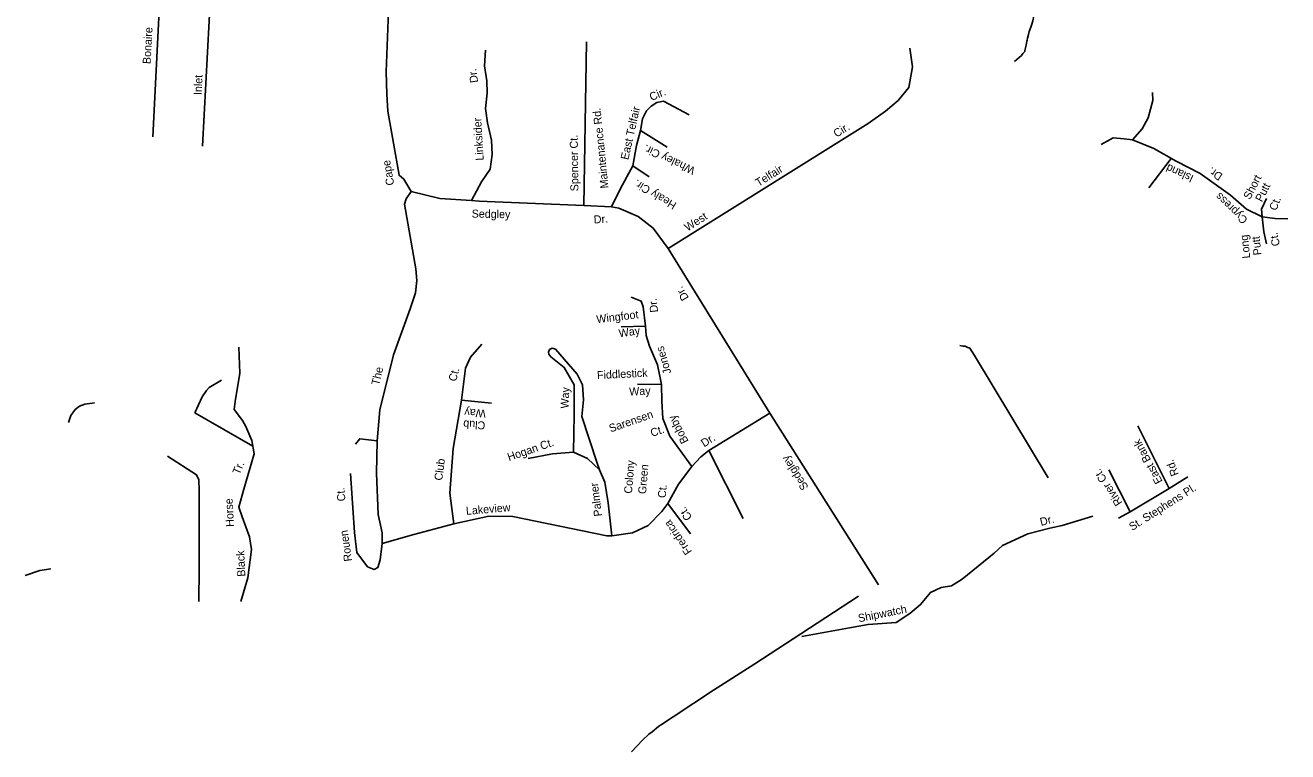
# Model space of a CAD drawing. Extents: x 2308163 to 2335412, y -96774 to 127732.
# Drawn here: x 2322672.99 to 2322693.21, y 104406.26 to 104417.9 of the extents above; entities that cross this region are included whole.
import ezdxf

# ---------------------------------------------------------------- set-up
doc = ezdxf.new("R2010")
doc.units = 0
doc.layers.add('Old_Level_10', color=7, linetype='Continuous')
doc.layers.add('Old_Level_35', color=7, linetype='Continuous')

msp = doc.modelspace()

# ---------------------------------------------------------------- linework, layer by layer
at = {"layer": 'Old_Level_35'}
for points in [[(2322675.83, 104415.962), (2322675.96, 104418.478), (2322676.033, 104419.348), (2322676.035, 104420.25), (2322676.11, 104421.179), (2322676.041, 104422.069), (2322676.047, 104422.656), (2322676.193, 104423.152), (2322676.251, 104423.594), (2322676.259, 104424.238)], [(2322675.033, 104416.113), (2322675.401, 104423.451), (2322675.323, 104424.098)], [(2322679.171, 104415.235), (2322679.055, 104415.435), (2322678.976, 104415.495), (2322678.798, 104416.524), (2322678.783, 104416.794), (2322678.771, 104417.155), (2322678.8, 104417.988), (2322678.79, 104418.201), (2322678.759, 104418.726), (2322678.726, 104419.169), (2322678.742, 104419.406), (2322678.832, 104419.64), (2322679.021, 104419.887), (2322679.16, 104420.128), (2322679.286, 104420.459), (2322679.438, 104421.059), (2322679.59, 104421.675), (2322679.797, 104422.47), (2322679.971, 104423.233), (2322680.03, 104423.664)], [(2322689.036, 104417.658), (2322689.046, 104417.691), (2322689.059, 104417.749), (2322689.072, 104417.8), (2322689.097, 104417.869), (2322689.118, 104417.935), (2322689.131, 104417.97), (2322689.135, 104417.997), (2322689.14, 104418.02), (2322689.136, 104418.056), (2322689.141, 104418.095), (2322689.126, 104418.248), (2322689.101, 104418.506), (2322689.068, 104418.796), (2322689.055, 104418.894), (2322689.055, 104419.023), (2322689.051, 104419.176), (2322689.06, 104419.429), (2322689.074, 104419.828), (2322689.099, 104420.394), (2322689.114, 104420.792)], [(2322681.936, 104415.013), (2322681.979, 104417.635)], [(2322683.287, 104414.32), (2322686.492, 104416.326), (2322686.769, 104416.521), (2322686.972, 104416.694), (2322687.142, 104416.9), (2322687.203, 104417.234), (2322687.156, 104417.53)], [(2322688.834, 104417.321), (2322688.945, 104417.415), (2322688.969, 104417.446), (2322688.989, 104417.47), (2322689.001, 104417.48), (2322689.002, 104417.496), (2322689.02, 104417.582), (2322689.033, 104417.644), (2322689.036, 104417.658)], [(2322680.361, 104417.501), (2322680.344, 104417.248), (2322680.385, 104417.009), (2322680.387, 104416.813), (2322680.362, 104416.568), (2322680.395, 104416.338), (2322680.459, 104416.058), (2322680.467, 104415.828), (2322680.435, 104415.592), (2322680.297, 104415.392), (2322680.139, 104415.092)], [(2322690.724, 104416.061), (2322690.879, 104416.238), (2322690.976, 104416.417), (2322691.052, 104416.696), (2322691.048, 104416.82)], [(2322682.377, 104414.99), (2322682.526, 104415.284), (2322682.719, 104415.646), (2322682.779, 104415.971), (2322682.845, 104416.214), (2322682.876, 104416.401), (2322682.938, 104416.53), (2322683.014, 104416.601), (2322683.106, 104416.663), (2322683.213, 104416.684), (2322683.623, 104416.466)], [(2322682.845, 104416.214), (2322683.27, 104415.946)], [(2322690.223, 104415.987), (2322690.418, 104416.096), (2322690.592, 104416.082), (2322690.724, 104416.061), (2322691.067, 104415.924), (2322691.425, 104415.722), (2322691.808, 104415.526), (2322692.294, 104415.178), (2322692.552, 104414.953), (2322692.804, 104414.829), (2322692.792, 104414.953), (2322692.873, 104415.125)], [(2322690.988, 104415.297), (2322691.347, 104415.766)], [(2322682.719, 104415.646), (2322682.983, 104415.473)], [(2322679.171, 104415.235), (2322679.093, 104415.116), (2322679.066, 104415.035), (2322679.243, 104413.999), (2322679.261, 104413.81), (2322679.238, 104413.614), (2322679.156, 104413.355), (2322678.885, 104412.62), (2322678.666, 104411.737), (2322678.624, 104411.24), (2322678.614, 104410.725), (2322678.641, 104410.061), (2322678.704, 104409.764), (2322678.706, 104409.593), (2322678.673, 104409.332), (2322678.636, 104409.21), (2322678.578, 104409.18), (2322678.473, 104409.224), (2322678.3, 104409.451), (2322678.262, 104409.771), (2322678.197, 104410.715)], [(2322683.666, 104410.827), (2322683.811, 104410.986), (2322683.937, 104411.088), (2322684.916, 104411.684), (2322683.287, 104414.32), (2322683.045, 104414.648), (2322682.806, 104414.836), (2322682.499, 104414.969), (2322682.377, 104414.99), (2322681.936, 104415.013), (2322680.261, 104415.079), (2322680.139, 104415.092), (2322679.632, 104415.126), (2322679.171, 104415.235)], [(2322692.804, 104414.829), (2322692.829, 104414.587), (2322692.872, 104414.395)], [(2322692.804, 104414.829), (2322693.011, 104414.805), (2322693.212, 104414.796)], [(2322678.706, 104409.593), (2322679.211, 104409.739), (2322679.856, 104409.913), (2322680.416, 104410.033), (2322680.801, 104410.028), (2322681.915, 104409.799), (2322682.305, 104409.72), (2322682.387, 104409.718), (2322682.716, 104409.764), (2322682.966, 104409.886), (2322683.186, 104410.107), (2322683.281, 104410.235), (2322683.452, 104410.548), (2322683.666, 104410.827), (2322683.315, 104411.314), (2322683.202, 104411.596), (2322683.187, 104411.874), (2322683.18, 104412.145), (2322683.117, 104412.458), (2322682.988, 104412.757), (2322682.936, 104412.93), (2322682.925, 104413.078), (2322682.887, 104413.39), (2322682.857, 104413.481), (2322682.696, 104413.544)], [(2322682.925, 104413.078), (2322682.532, 104413.067)], [(2322676.442, 104408.665), (2322676.556, 104409.044), (2322676.615, 104409.5), (2322676.579, 104409.702), (2322676.461, 104410.021), (2322676.409, 104410.18), (2322676.49, 104410.464), (2322676.653, 104411.031), (2322676.618, 104411.247), (2322676.521, 104411.472), (2322676.471, 104411.567), (2322676.334, 104411.743), (2322676.352, 104411.872), (2322676.426, 104412.327), (2322676.411, 104412.743)], [(2322679.856, 104409.913), (2322679.792, 104410.401), (2322679.841, 104411.119), (2322679.975, 104411.892), (2322680.041, 104412.405), (2322680.121, 104412.582), (2322680.3, 104412.789)], [(2322681.772, 104411.061), (2322681.784, 104411.658), (2322681.784, 104412.14), (2322681.622, 104412.416), (2322681.407, 104412.587), (2322681.375, 104412.629), (2322681.368, 104412.662), (2322681.386, 104412.702), (2322681.428, 104412.725), (2322681.485, 104412.707), (2322681.831, 104412.311), (2322681.915, 104412.136), (2322681.931, 104411.898), (2322681.906, 104411.629), (2322682.143, 104410.901), (2322682.188, 104410.777)], [(2322689.372, 104410.648), (2322688.79, 104411.616), (2322688.192, 104412.607), (2322688.121, 104412.723), (2322688.09, 104412.738), (2322688.047, 104412.755), (2322688.008, 104412.76), (2322687.958, 104412.769)], [(2322675.705, 104411.691), (2322675.824, 104411.944), (2322675.893, 104412.046), (2322675.934, 104412.096), (2322676.131, 104412.213)], [(2322683.18, 104412.145), (2322682.795, 104412.15)], [(2322673.683, 104411.533), (2322673.72, 104411.646), (2322673.789, 104411.743), (2322673.86, 104411.794), (2322673.944, 104411.83), (2322674.097, 104411.85)], [(2322679.975, 104411.892), (2322680.456, 104411.843)], [(2322675.705, 104411.691), (2322676.632, 104411.156)], [(2322684.916, 104411.684), (2322686.654, 104408.934)], [(2322690.809, 104411.481), (2322691.314, 104410.477), (2322691.611, 104410.666)], [(2322678.624, 104411.24), (2322678.347, 104411.274), (2322678.278, 104411.186)], [(2322682.387, 104409.718), (2322682.325, 104410.248), (2322682.271, 104410.577), (2322682.188, 104410.777), (2322681.997, 104410.955), (2322681.772, 104411.061), (2322681.435, 104411.032), (2322681.047, 104410.955)], [(2322683.937, 104411.088), (2322684.489, 104409.997)], [(2322675.266, 104410.997), (2322675.732, 104410.697), (2322675.768, 104410.616), (2322675.776, 104410.443), (2322675.772, 104409.194), (2322675.771, 104408.667)], [(2322690.687, 104410.101), (2322690.346, 104410.776)], [(2322691.314, 104410.477), (2322690.687, 104410.101), (2322690.501, 104410)], [(2322683.281, 104410.235), (2322683.645, 104409.748)], [(2322685.43, 104408.103), (2322686.191, 104408.242), (2322686.491, 104408.298), (2322686.94, 104408.332), (2322687.161, 104408.474), (2322687.332, 104408.617), (2322687.488, 104408.811), (2322687.66, 104408.888), (2322687.826, 104408.915), (2322687.996, 104409.025), (2322688.508, 104409.439), (2322688.645, 104409.566), (2322689.05, 104409.751), (2322689.401, 104409.839), (2322689.601, 104409.882), (2322690.088, 104410.031)], [(2322672.989, 104409.083), (2322673.22, 104409.165), (2322673.399, 104409.188)], [(2322686.338, 104408.751), (2322685.413, 104408.147), (2322684.675, 104407.669), (2322684.016, 104407.243), (2322683.368, 104406.817), (2322683.178, 104406.693), (2322683.134, 104406.666), (2322683.031, 104406.579), (2322682.978, 104406.541), (2322682.874, 104406.442), (2322682.7, 104406.259)]]:
    msp.add_lwpolyline(points, dxfattribs=at)

# ---------------------------------------------------------------- texts
at = {"layer": 'Old_Level_10'}
for s, height, rotation, p in [('Bonaire', 0.1282, 86.8529, (2322674.996, 104417.275)), ('Dr.', 0.1282, 98.3115, (2322680.244, 104416.986)), ('Inlet', 0.1282, 87.8162, (2322675.816, 104416.779)), ('Cir.', 0.1282, 22.8854, (2322683.019, 104416.684)), ('Maintenance Rd.', 0.12816, 95.7048, (2322682.332, 104415.291)), ('East Telfair ', 0.12816, 77.2768, (2322682.648, 104415.735)), ('Linksider', 0.1282, 93.4684, (2322680.333, 104415.735)), ('Spencer Ct.', 0.12816, 90.7324, (2322681.85, 104415.239)), ('Cir.', 0.1282, 31.7692, (2322685.984, 104416.097)), ('Whaley Cir.', 0.12816, 154.835, (2322683.732, 104415.615)), ('Cape', 0.1282, 99.9628, (2322678.901, 104415.344)), ('Telfair', 0.1282, 31.8069, (2322684.734, 104415.31)), (' Island ', 0.1282, 155.2034, (2322691.759, 104415.47)), ('Dr.', 0.1282, 146.8638, (2322692.18, 104415.509)), ('Short', 0.1282, 62.5056, (2322692.607, 104415.097)), ('Healy Cir.', 0.1282, 149.1209, (2322683.432, 104415.048)), ('Putt', 0.1282, 62.5056, (2322692.797, 104415.059)), ('Cypress', 0.1282, 136.1992, (2322692.581, 104414.793)), ('Ct.', 0.1282, 68.6681, (2322693.028, 104414.919)), ('Sedgley', 0.1282, 358.9794, (2322680.139, 104414.818)), ('West', 0.1282, 32.3643, (2322683.597, 104414.594)), ('Dr.', 0.1282, 3.7721, (2322682.099, 104414.722)), ('Long', 0.1282, 95.9768, (2322692.612, 104414.169)), ('Putt', 0.1282, 95.9768, (2322692.793, 104414.221)), ('Ct.', 0.1282, 101.7692, (2322693.089, 104414.374)), ('Dr.', 0.1282, 121.0201, (2322683.623, 104413.533)), ('Dr.', 0.1282, 96.5311, (2322683.127, 104413.304)), ('Wingfoot ', 0.1282, 6.8876, (2322682.145, 104413.125)), ('Way', 0.1282, 8.3091, (2322682.505, 104412.899)), ('Jones', 0.1282, 106.3222, (2322683.338, 104412.33)), ('The ', 0.1282, 76.327, (2322678.655, 104412.122)), ('Ct.', 0.1282, 75.0685, (2322679.888, 104412.183)), ('Fiddlestick', 0.12816, 2.8383, (2322682.151, 104412.229)), ('Way', 0.1282, 87.7119, (2322681.691, 104411.756)), ('Way', 0.1282, 2.8383, (2322682.666, 104411.965)), ('Way', 0.1282, 176.6967, (2322680.369, 104411.739)), ('Sarensen', 0.1282, 19.2289, (2322682.366, 104411.374)), ('Club', 0.1282, 176.6967, (2322680.361, 104411.549)), ('Ct.', 0.1282, 19.2289, (2322683.029, 104411.302)), ('Bobby', 0.1282, 117.1145, (2322683.617, 104411.234)), ('Hogan Ct.', 0.1282, 19.0033, (2322680.738, 104410.914)), ('Dr.', 0.1282, 32.3018, (2322683.864, 104411.135)), ('East Bank', 0.1282, 118.3259, (2322691.211, 104410.591)), ('Tr.', 0.1282, 66.8835, (2322676.42, 104410.689)), ('Club ', 0.1282, 82.3139, (2322679.666, 104410.598)), ('Colony', 0.1282, 85.3278, (2322682.707, 104410.391)), ('Green ', 0.1282, 85.3278, (2322682.932, 104410.384)), ('Sedgley', 0.1282, 122.9112, (2322685.54, 104410.501)), ('Rd.', 0.1282, 110.7645, (2322691.469, 104410.704)), ('River Ct.', 0.1282, 123.4059, (2322690.569, 104410.249)), ('Ct.', 0.1282, 94.6733, (2322678.118, 104410.276)), ('Palmer', 0.1282, 97.0173, (2322682.228, 104410.037)), ('Ct.', 0.1282, 85.3278, (2322683.248, 104410.321)), ('St. Stephens Pl.', 0.12816, 32.4762, (2322690.72, 104409.795)), ('Horse', 0.1282, 92.966, (2322676.333, 104409.865)), ('Lakeview', 0.1282, 4.7502, (2322680.053, 104410.054)), ('Ct.', 0.1282, 124.4823, (2322683.677, 104410.016)), ('Fredrica', 0.1282, 124.4823, (2322683.674, 104409.468)), ('Dr.', 0.1282, 14.4843, (2322689.261, 104409.876)), ('Rouen', 0.1282, 98.3217, (2322678.224, 104409.317)), ('Black', 0.1282, 92.67, (2322676.515, 104409.067)), ('Shipwatch', 0.1282, 11.3903, (2322686.343, 104408.332))]:
    msp.add_text(s, height=height, rotation=rotation, dxfattribs=at).set_placement(p)

doc.saveas('drawing.dxf')
